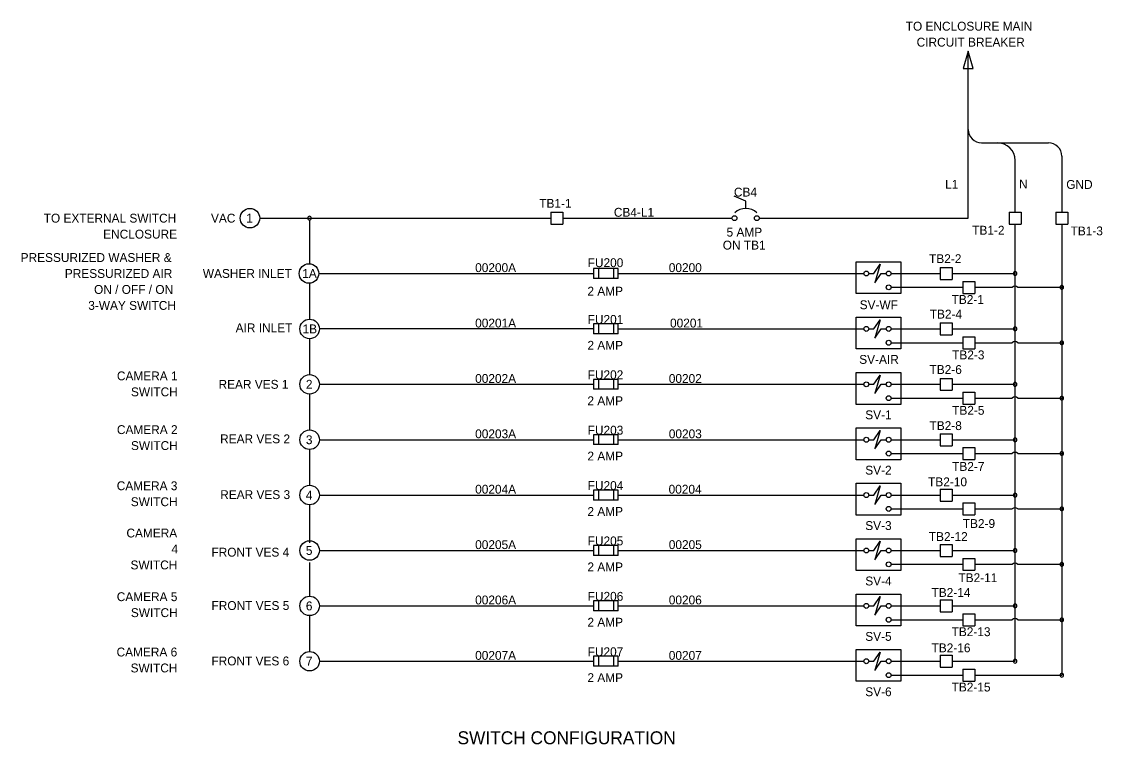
# Model space of a CAD drawing. Extents: x 0.82 to 2.03, y 0.91 to 1.72.
import ezdxf

# ---------------------------------------------------------------- set-up
doc = ezdxf.new("R2010")
doc.units = 0
for name, color, linetype in [('Default', 7, 'Continuous'), ('Sheets_General Details - Sheet Number Text', 7, 'Continuous'), ('Sheets_General Details - Total Sheet Number Text', 7, 'Continuous'), ('Sheets_General Details - Version Text', 7, 'Continuous')]:
    doc.layers.add(name, color=color, linetype=linetype)

# ---------------------------------------------------------------- blocks, each defined once
blk = doc.blocks.new('DOT-F')
at = {"layer": 'Default'}
for start, end in [(0, 180), (180, 0)]:
    blk.add_arc((0, 0), 0.000397, start, end, dxfattribs=at)
blk = doc.blocks.new('ARROW')
at = {"layer": 'Default'}
blk.add_lwpolyline([(0, 0), (-0.00556, 0.00159), (-0.00556, -0.00159)], close=True, dxfattribs=at)

msp = doc.modelspace()

# ---------------------------------------------------------------- linework, layer by layer
at = {"layer": 'Sheets_General Details - Sheet Number Text'}
for p, q in [((1.8822, 1.4994), (1.8822, 1.6878)), ((1.8971, 1.5845), (1.915, 1.5845)), ((1.915, 1.5845), (1.9726, 1.5845)), ((1.9349, 1.5062), (1.9349, 1.5646)), ((1.9875, 1.5695), (1.9875, 1.5062)), ((1.0837, 1.4994), (1.4119, 1.4994)), ((1.4253, 1.4994), (1.6159, 1.4994)), ((1.6467, 1.4994), (1.8822, 1.4994)), ((1.9349, 0.9997), (1.9349, 1.4927)), ((1.9875, 1.4927), (1.9875, 0.984)), ((1.151, 1.437), (1.4596, 1.437)), ((1.4876, 1.437), (1.7645, 1.437)), ((1.7953, 1.437), (1.8505, 1.437)), ((1.8639, 1.437), (1.9349, 1.437)), ((1.7953, 1.4214), (1.876, 1.4214)), ((1.8894, 1.4214), (1.9316, 1.4214)), ((1.9381, 1.4214), (1.9875, 1.4214)), ((1.4598, 1.3745), (1.151, 1.3745)), ((1.4876, 1.3745), (1.7645, 1.3745)), ((1.7953, 1.3745), (1.8505, 1.3745)), ((1.8639, 1.3745), (1.9349, 1.3745)), ((1.7953, 1.3589), (1.876, 1.3589)), ((1.8894, 1.3589), (1.9316, 1.3589)), ((1.9381, 1.3589), (1.9875, 1.3589)), ((1.151, 1.312), (1.4596, 1.312)), ((1.4876, 1.312), (1.7645, 1.312)), ((1.7953, 1.312), (1.8505, 1.312)), ((1.8639, 1.312), (1.9349, 1.312)), ((1.7953, 1.2964), (1.876, 1.2964)), ((1.8894, 1.2964), (1.9316, 1.2964)), ((1.9381, 1.2964), (1.9875, 1.2964)), ((1.1515, 1.2495), (1.4596, 1.2495)), ((1.4876, 1.2495), (1.7645, 1.2495)), ((1.7953, 1.2495), (1.8505, 1.2495)), ((1.8639, 1.2495), (1.9349, 1.2495)), ((1.7953, 1.2339), (1.876, 1.2339)), ((1.8894, 1.2339), (1.9316, 1.2339)), ((1.9381, 1.2339), (1.9875, 1.2339)), ((1.151, 1.1871), (1.4596, 1.1871)), ((1.4876, 1.1871), (1.7645, 1.1871)), ((1.7953, 1.1871), (1.8505, 1.1871)), ((1.8639, 1.1871), (1.9349, 1.1871)), ((1.7953, 1.1715), (1.876, 1.1715)), ((1.8894, 1.1715), (1.9316, 1.1715)), ((1.9381, 1.1715), (1.9875, 1.1715)), ((1.151, 1.1246), (1.4598, 1.1246)), ((1.4876, 1.1246), (1.7645, 1.1246)), ((1.7953, 1.1246), (1.8505, 1.1246)), ((1.8639, 1.1246), (1.9349, 1.1246)), ((1.7953, 1.109), (1.876, 1.109)), ((1.8894, 1.109), (1.9316, 1.109)), ((1.9381, 1.109), (1.9875, 1.109)), ((1.151, 1.0621), (1.4596, 1.0621)), ((1.4876, 1.0621), (1.7645, 1.0621)), ((1.7953, 1.0621), (1.8505, 1.0621)), ((1.8639, 1.0621), (1.9349, 1.0621)), ((1.7953, 1.0465), (1.876, 1.0465)), ((1.8894, 1.0465), (1.9316, 1.0465)), ((1.9381, 1.0465), (1.9875, 1.0465)), ((1.151, 0.9997), (1.4596, 0.9997)), ((1.4876, 0.9997), (1.7645, 0.9997)), ((1.7953, 0.9997), (1.8505, 0.9997)), ((1.8639, 0.9997), (1.9349, 0.9997)), ((1.7953, 0.984), (1.876, 0.984)), ((1.8894, 0.984), (1.9381, 0.984)), ((1.9381, 0.984), (1.9875, 0.984))]:
    msp.add_line(p, q, dxfattribs=at)
for centre, radius, start, end in [((1.8971, 1.5994), 0.0149, 180, 270), ((1.915, 1.5646), 0.0199, 360, 90), ((1.9726, 1.5695), 0.0149, 360, 90), ((1.9349, 1.418), 0.00466, 45.849, 134.151), ((1.9349, 1.3555), 0.00466, 45.849, 134.151), ((1.9349, 1.2931), 0.00466, 45.849, 134.151), ((1.9349, 1.2306), 0.00466, 45.849, 134.151), ((1.9349, 1.1681), 0.00466, 45.849, 134.151), ((1.9349, 1.1056), 0.00466, 45.849, 134.151), ((1.9349, 1.0432), 0.00466, 45.849, 134.151)]:
    msp.add_arc(centre, radius, start, end, dxfattribs=at)
at = {"layer": 'Sheets_General Details - Total Sheet Number Text'}
for p, q in [((1.1399, 1.4975), (1.1399, 1.448)), ((1.1399, 1.4259), (1.1399, 1.3855)), ((1.1399, 1.3635), (1.1399, 1.3231)), ((1.1399, 1.301), (1.1399, 1.2606)), ((1.1399, 1.2385), (1.1399, 1.1981)), ((1.1399, 1.176), (1.1399, 1.1333)), ((1.1399, 1.1112), (1.1399, 1.0732)), ((1.1399, 1.0511), (1.1399, 1.0107))]:
    msp.add_line(p, q, dxfattribs=at)
for centre in [(1.0727, 1.4994), (1.1392, 1.437), (1.1399, 1.3745), (1.1399, 1.312), (1.1399, 1.2495), (1.1399, 1.1871), (1.1399, 1.1246), (1.1399, 1.0621), (1.1399, 0.9997)]:
    msp.add_circle(centre, 0.011, dxfattribs=at)
at = {"layer": 'Sheets_General Details - Version Text'}
for p, q in [((1.6315, 1.5184), (1.6185, 1.5244)), ((1.6315, 1.5104), (1.6315, 1.5184)), ((1.4119, 1.5062), (1.4253, 1.5062)), ((1.4119, 1.5062), (1.4119, 1.4927)), ((1.4253, 1.5062), (1.4253, 1.4927)), ((1.9281, 1.5062), (1.9416, 1.5062)), ((1.9281, 1.5062), (1.9281, 1.4927)), ((1.9416, 1.5062), (1.9416, 1.4927)), ((1.9808, 1.5062), (1.9942, 1.5062)), ((1.9808, 1.5062), (1.9808, 1.4927)), ((1.9942, 1.5062), (1.9942, 1.4927)), ((1.4119, 1.4927), (1.4253, 1.4927)), ((1.9281, 1.4927), (1.9416, 1.4927)), ((1.9808, 1.4927), (1.9942, 1.4927)), ((1.4878, 1.4426), (1.4598, 1.4426)), ((1.4598, 1.4426), (1.4598, 1.4314)), ((1.4654, 1.4426), (1.4654, 1.4314)), ((1.4822, 1.4426), (1.4822, 1.4314)), ((1.4878, 1.4314), (1.4878, 1.4426)), ((1.7756, 1.437), (1.7828, 1.4474)), ((1.7828, 1.4474), (1.777, 1.4265)), ((1.8505, 1.4437), (1.8639, 1.4437)), ((1.8505, 1.4437), (1.8505, 1.4303)), ((1.8639, 1.4437), (1.8639, 1.4303)), ((1.4878, 1.4314), (1.4598, 1.4314)), ((1.7701, 1.437), (1.7756, 1.437)), ((1.777, 1.4265), (1.7842, 1.437)), ((1.7842, 1.437), (1.7897, 1.437)), ((1.8505, 1.4303), (1.8639, 1.4303)), ((1.876, 1.4281), (1.8894, 1.4281)), ((1.876, 1.4281), (1.876, 1.4146)), ((1.8894, 1.4281), (1.8894, 1.4146)), ((1.876, 1.4146), (1.8894, 1.4146)), ((1.4878, 1.3801), (1.4598, 1.3801)), ((1.4598, 1.3801), (1.4598, 1.3689)), ((1.4654, 1.3801), (1.4654, 1.3689)), ((1.4822, 1.3801), (1.4822, 1.3689)), ((1.4878, 1.3689), (1.4878, 1.3801)), ((1.7756, 1.3745), (1.7828, 1.3849)), ((1.7828, 1.3849), (1.777, 1.3641)), ((1.8505, 1.3812), (1.8639, 1.3812)), ((1.8505, 1.3812), (1.8505, 1.3678)), ((1.8639, 1.3812), (1.8639, 1.3678)), ((1.4878, 1.3689), (1.4598, 1.3689)), ((1.7701, 1.3745), (1.7756, 1.3745)), ((1.777, 1.3641), (1.7842, 1.3745)), ((1.7842, 1.3745), (1.7897, 1.3745)), ((1.8505, 1.3678), (1.8639, 1.3678)), ((1.876, 1.3656), (1.8894, 1.3656)), ((1.876, 1.3656), (1.876, 1.3522)), ((1.8894, 1.3656), (1.8894, 1.3522)), ((1.876, 1.3522), (1.8894, 1.3522)), ((1.4598, 1.3176), (1.4598, 1.3064)), ((1.4878, 1.3176), (1.4598, 1.3176)), ((1.4654, 1.3176), (1.4654, 1.3064)), ((1.4822, 1.3176), (1.4822, 1.3064)), ((1.4878, 1.3064), (1.4878, 1.3176)), ((1.7756, 1.312), (1.7828, 1.3225)), ((1.7828, 1.3225), (1.777, 1.3016)), ((1.8505, 1.3187), (1.8639, 1.3187)), ((1.8505, 1.3187), (1.8505, 1.3053)), ((1.8639, 1.3187), (1.8639, 1.3053)), ((1.4878, 1.3064), (1.4598, 1.3064)), ((1.7701, 1.312), (1.7756, 1.312)), ((1.777, 1.3016), (1.7842, 1.312)), ((1.7842, 1.312), (1.7897, 1.312)), ((1.8505, 1.3053), (1.8639, 1.3053)), ((1.876, 1.3031), (1.8894, 1.3031)), ((1.876, 1.3031), (1.876, 1.2897)), ((1.8894, 1.3031), (1.8894, 1.2897)), ((1.876, 1.2897), (1.8894, 1.2897)), ((1.4598, 1.2551), (1.4598, 1.244)), ((1.4878, 1.2551), (1.4598, 1.2551)), ((1.4654, 1.2551), (1.4654, 1.244)), ((1.4822, 1.2551), (1.4822, 1.244)), ((1.4878, 1.244), (1.4878, 1.2551)), ((1.7756, 1.2495), (1.7828, 1.26)), ((1.7828, 1.26), (1.777, 1.2391)), ((1.8505, 1.2563), (1.8639, 1.2563)), ((1.8505, 1.2563), (1.8505, 1.2428)), ((1.8639, 1.2563), (1.8639, 1.2428)), ((1.4878, 1.244), (1.4598, 1.244)), ((1.7701, 1.2495), (1.7756, 1.2495)), ((1.777, 1.2391), (1.7842, 1.2495)), ((1.7842, 1.2495), (1.7897, 1.2495)), ((1.8505, 1.2428), (1.8639, 1.2428)), ((1.876, 1.2407), (1.8894, 1.2407)), ((1.876, 1.2407), (1.876, 1.2272)), ((1.8894, 1.2407), (1.8894, 1.2272)), ((1.876, 1.2272), (1.8894, 1.2272)), ((1.7756, 1.1871), (1.7828, 1.1975)), ((1.7828, 1.1975), (1.777, 1.1766)), ((1.8505, 1.1938), (1.8639, 1.1938)), ((1.8505, 1.1938), (1.8505, 1.1804)), ((1.8639, 1.1938), (1.8639, 1.1804)), ((1.4598, 1.1927), (1.4598, 1.1815)), ((1.4878, 1.1927), (1.4598, 1.1927)), ((1.4878, 1.1815), (1.4598, 1.1815)), ((1.4654, 1.1927), (1.4654, 1.1815)), ((1.4822, 1.1927), (1.4822, 1.1815)), ((1.4878, 1.1815), (1.4878, 1.1927)), ((1.7701, 1.1871), (1.7756, 1.1871)), ((1.777, 1.1766), (1.7842, 1.1871)), ((1.7842, 1.1871), (1.7897, 1.1871)), ((1.8505, 1.1804), (1.8639, 1.1804)), ((1.876, 1.1782), (1.8894, 1.1782)), ((1.876, 1.1782), (1.876, 1.1648)), ((1.8894, 1.1782), (1.8894, 1.1648)), ((1.876, 1.1648), (1.8894, 1.1648)), ((1.7756, 1.1246), (1.7828, 1.135)), ((1.7828, 1.135), (1.777, 1.1142)), ((1.4878, 1.1302), (1.4598, 1.1302)), ((1.4598, 1.1302), (1.4598, 1.119)), ((1.4654, 1.1302), (1.4654, 1.119)), ((1.4822, 1.1302), (1.4822, 1.119)), ((1.4878, 1.119), (1.4878, 1.1302)), ((1.7701, 1.1246), (1.7756, 1.1246)), ((1.777, 1.1142), (1.7842, 1.1246)), ((1.7842, 1.1246), (1.7897, 1.1246)), ((1.8505, 1.1313), (1.8639, 1.1313)), ((1.8505, 1.1313), (1.8505, 1.1179)), ((1.8639, 1.1313), (1.8639, 1.1179)), ((1.4878, 1.119), (1.4598, 1.119)), ((1.8505, 1.1179), (1.8639, 1.1179)), ((1.876, 1.1157), (1.8894, 1.1157)), ((1.876, 1.1157), (1.876, 1.1023)), ((1.8894, 1.1157), (1.8894, 1.1023)), ((1.876, 1.1023), (1.8894, 1.1023)), ((1.7756, 1.0621), (1.7828, 1.0726)), ((1.7828, 1.0726), (1.777, 1.0517)), ((1.4878, 1.0677), (1.4598, 1.0677)), ((1.4598, 1.0677), (1.4598, 1.0565)), ((1.4654, 1.0677), (1.4654, 1.0565)), ((1.4822, 1.0677), (1.4822, 1.0565)), ((1.4878, 1.0565), (1.4878, 1.0677)), ((1.7701, 1.0621), (1.7756, 1.0621)), ((1.777, 1.0517), (1.7842, 1.0621)), ((1.7842, 1.0621), (1.7897, 1.0621)), ((1.8505, 1.0688), (1.8639, 1.0688)), ((1.8505, 1.0688), (1.8505, 1.0554)), ((1.8639, 1.0688), (1.8639, 1.0554)), ((1.4878, 1.0565), (1.4598, 1.0565)), ((1.8505, 1.0554), (1.8639, 1.0554)), ((1.876, 1.0532), (1.8894, 1.0532)), ((1.876, 1.0532), (1.876, 1.0398)), ((1.8894, 1.0532), (1.8894, 1.0398)), ((1.876, 1.0398), (1.8894, 1.0398)), ((1.4878, 1.0053), (1.4598, 1.0053)), ((1.4598, 1.0053), (1.4598, 0.9941)), ((1.4654, 1.0053), (1.4654, 0.9941)), ((1.4822, 1.0053), (1.4822, 0.9941)), ((1.4878, 0.9941), (1.4878, 1.0053)), ((1.7701, 0.9997), (1.7756, 0.9997)), ((1.7756, 0.9997), (1.7828, 1.0101)), ((1.7828, 1.0101), (1.777, 0.9892)), ((1.777, 0.9892), (1.7842, 0.9997)), ((1.7842, 0.9997), (1.7897, 0.9997)), ((1.8505, 1.0064), (1.8639, 1.0064)), ((1.8505, 1.0064), (1.8505, 0.9929)), ((1.8639, 1.0064), (1.8639, 0.9929)), ((1.4878, 0.9941), (1.4598, 0.9941)), ((1.8505, 0.9929), (1.8639, 0.9929)), ((1.876, 0.9908), (1.8894, 0.9908)), ((1.876, 0.9908), (1.876, 0.9773)), ((1.8894, 0.9908), (1.8894, 0.9773)), ((1.876, 0.9773), (1.8894, 0.9773))]:
    msp.add_line(p, q, dxfattribs=at)
for points in [[(1.7559, 1.4503), (1.8061, 1.4503), (1.8061, 1.4144), (1.7559, 1.4144)], [(1.7559, 1.3878), (1.8061, 1.3878), (1.8061, 1.3519), (1.7559, 1.3519)], [(1.7559, 1.3253), (1.8061, 1.3253), (1.8061, 1.2894), (1.7559, 1.2894)], [(1.7559, 1.2629), (1.8061, 1.2629), (1.8061, 1.227), (1.7559, 1.227)], [(1.7559, 1.2004), (1.8061, 1.2004), (1.8061, 1.1645), (1.7559, 1.1645)], [(1.7559, 1.1379), (1.8061, 1.1379), (1.8061, 1.102), (1.7559, 1.102)], [(1.7559, 1.0755), (1.8061, 1.0755), (1.8061, 1.0395), (1.7559, 1.0395)], [(1.7559, 1.013), (1.8061, 1.013), (1.8061, 0.9771), (1.7559, 0.9771)]]:
    msp.add_lwpolyline(points, close=True, dxfattribs=at)
for centre in [(1.6187, 1.4994), (1.6439, 1.4994), (1.7673, 1.437), (1.7925, 1.437), (1.7925, 1.4214), (1.7673, 1.3745), (1.7925, 1.3745), (1.7925, 1.3589), (1.7673, 1.312), (1.7925, 1.312), (1.7925, 1.2964), (1.7673, 1.2495), (1.7925, 1.2495), (1.7925, 1.2339), (1.7673, 1.1871), (1.7925, 1.1871), (1.7925, 1.1715), (1.7673, 1.1246), (1.7925, 1.1246), (1.7925, 1.109), (1.7673, 1.0621), (1.7925, 1.0621), (1.7925, 1.0465), (1.7673, 0.9997), (1.7925, 0.9997), (1.7925, 0.984)]:
    msp.add_circle(centre, 0.00279, dxfattribs=at)
msp.add_arc((1.6315, 1.4923), 0.0181, 46.3583, 133.6417, dxfattribs=at)

# ---------------------------------------------------------------- block references
at = {"layer": 'Sheets_General Details - Sheet Number Text'}
for name, p, xscale, yscale, rotation in [('ARROW', (1.8822, 1.6878), 3.524598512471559, 3.524598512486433, 89.99999999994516), ('DOT-F', (1.1399, 1.4994), 5.28689776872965, 5.286897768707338, -5.484581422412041e-11), ('DOT-F', (1.9349, 1.437), 5.28689776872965, 5.286897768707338, -5.484581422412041e-11), ('DOT-F', (1.9875, 1.4214), 5.28689776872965, 5.286897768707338, -5.484581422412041e-11), ('DOT-F', (1.9349, 1.3745), 5.28689776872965, 5.286897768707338, -5.484581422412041e-11), ('DOT-F', (1.9875, 1.3589), 5.28689776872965, 5.286897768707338, -5.484581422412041e-11), ('DOT-F', (1.9349, 1.312), 5.28689776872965, 5.286897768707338, -5.484581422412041e-11), ('DOT-F', (1.9875, 1.2964), 5.28689776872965, 5.286897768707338, -5.484581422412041e-11), ('DOT-F', (1.9349, 1.2495), 5.28689776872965, 5.286897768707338, -5.484581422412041e-11), ('DOT-F', (1.9875, 1.2339), 5.28689776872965, 5.286897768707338, -5.484581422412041e-11), ('DOT-F', (1.9349, 1.1871), 5.28689776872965, 5.286897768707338, -5.484581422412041e-11), ('DOT-F', (1.9875, 1.1715), 5.28689776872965, 5.286897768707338, -5.484581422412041e-11), ('DOT-F', (1.9349, 1.1246), 5.28689776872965, 5.286897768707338, -5.484581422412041e-11), ('DOT-F', (1.9875, 1.109), 5.28689776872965, 5.286897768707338, -5.484581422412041e-11), ('DOT-F', (1.9349, 1.0621), 5.28689776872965, 5.286897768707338, -5.484581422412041e-11), ('DOT-F', (1.9875, 1.0465), 5.28689776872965, 5.286897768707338, -5.484581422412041e-11), ('DOT-F', (1.9349, 0.9997), 5.28689776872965, 5.286897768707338, -5.484581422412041e-11), ('DOT-F', (1.9875, 0.984), 5.28689776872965, 5.286897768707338, -5.484581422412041e-11)]:
    msp.add_blockref(name, p, dxfattribs=dict(at, xscale=xscale, yscale=yscale, rotation=rotation))

# ---------------------------------------------------------------- texts
at = {"layer": 'Sheets_General Details - Total Sheet Number Text'}
for s, p in [('TO ENCLOSURE MAIN ', (1.8117, 1.7109)), ('CIRCUIT BREAKER', (1.824, 1.6929)), ('L1', (1.8561, 1.5326)), ('N', (1.9394, 1.5329)), ('GND', (1.9926, 1.5324)), ('CB4', (1.6181, 1.5238)), ('TB1-1', (1.3987, 1.5111)), ('CB4-L1', (1.4828, 1.501)), ('TO EXTERNAL SWITCH', (0.8403, 1.4944)), ('VAC', (1.0288, 1.4944)), ('1', (1.0685, 1.4944)), (' ENCLOSURE', (0.9036, 1.4764)), ('5 AMP', (1.6098, 1.4786)), ('TB1-2', (1.8866, 1.4808)), ('TB1-3', (1.9975, 1.48)), ('ON TB1', (1.6055, 1.464)), ('PRESSURIZED WASHER & ', (0.8143, 1.45)), ('FU200', (1.4533, 1.4442)), ('TB2-2', (1.838, 1.4487)), ('PRESSURIZED AIR ', (0.8641, 1.432)), ('WASHER INLET', (1.0196, 1.432)), ('1A', (1.1316, 1.432)), ('00200A', (1.3265, 1.4386)), ('00200', (1.5447, 1.4386)), ('ON / OFF / ON ', (0.897, 1.414)), ('2 AMP', (1.453, 1.4121)), ('TB2-1', (1.8634, 1.4027)), ('3-WAY SWITCH', (0.8905, 1.396)), ('SV-WF', (1.7598, 1.3967)), ('FU201', (1.4533, 1.3802)), ('TB2-4', (1.8388, 1.3862)), ('AIR INLET', (1.0566, 1.3707)), ('1B', (1.132, 1.3695)), ('00201A', (1.3265, 1.3761)), ('00201', (1.5461, 1.3761)), ('2 AMP', (1.453, 1.351)), ('SV-AIR', (1.7593, 1.3351)), ('TB2-3', (1.864, 1.3402)), ('FU202', (1.4533, 1.3178)), ('TB2-6', (1.8385, 1.3237)), ('CAMERA 1', (0.9228, 1.3165)), ('REAR VES 1', (1.0373, 1.307)), ('2', (1.1357, 1.307)), ('00202A', (1.3265, 1.3136)), ('00202', (1.5447, 1.3136)), (' SWITCH', (0.9349, 1.2985)), ('2 AMP', (1.453, 1.2885)), ('SV-1', (1.7661, 1.2726)), ('TB2-5', (1.864, 1.2777)), ('TB2-8', (1.8385, 1.2604)), ('CAMERA 2', (0.9228, 1.2559)), ('REAR VES 2', (1.0391, 1.2455)), ('3', (1.1357, 1.2445)), ('00203A', (1.3265, 1.2512)), ('FU203', (1.4533, 1.2553)), ('00203', (1.5447, 1.2512)), (' SWITCH', (0.9349, 1.2379)), ('2 AMP', (1.453, 1.2261)), ('SV-2', (1.7661, 1.2102)), ('TB2-7', (1.864, 1.2144)), ('TB2-10', (1.8369, 1.197)), ('CAMERA 3', (0.9226, 1.1926)), ('00204A', (1.3265, 1.1887)), ('FU204', (1.4533, 1.1928)), ('00204', (1.5445, 1.1887)), (' SWITCH', (0.9347, 1.1746)), ('REAR VES 3', (1.0392, 1.1826)), ('4', (1.1357, 1.1821)), ('2 AMP', (1.453, 1.1636)), ('SV-3', (1.7661, 1.1477)), ('TB2-9', (1.876, 1.15)), ('CAMERA', (0.9335, 1.1393)), ('TB2-12', (1.8377, 1.1353)), ('00205A', (1.3265, 1.1262)), ('FU205', (1.4533, 1.1304)), ('00205', (1.5447, 1.1262)), (' 4', (0.9805, 1.1213)), ('FRONT VES 4', (1.0293, 1.1177)), ('5', (1.1357, 1.1196)), (' SWITCH', (0.9344, 1.1033)), ('2 AMP', (1.453, 1.1011)), ('TB2-11', (1.8711, 1.0889)), ('SV-4', (1.7661, 1.0852)), ('CAMERA 5', (0.9226, 1.0675)), ('00206A', (1.3265, 1.0638)), ('FU206', (1.4533, 1.0679)), ('00206', (1.5447, 1.0638)), ('TB2-14', (1.8408, 1.0723)), (' SWITCH', (0.9348, 1.0495)), ('FRONT VES 5', (1.0294, 1.0575)), ('6', (1.1357, 1.0571)), ('2 AMP', (1.453, 1.0387)), ('TB2-13', (1.8634, 1.028)), ('SV-5', (1.7661, 1.0227)), ('CAMERA 6', (0.9224, 1.0051)), ('00207A', (1.3265, 1.0013)), ('FU207', (1.4533, 1.0054)), ('00207', (1.5447, 1.0013)), ('TB2-16', (1.8408, 1.0098)), ('FRONT VES 6', (1.0293, 0.995)), ('7', (1.1357, 0.9947)), (' SWITCH', (0.9345, 0.9871)), ('2 AMP', (1.453, 0.9762)), ('TB2-15', (1.8634, 0.9656)), ('SV-6', (1.7661, 0.9603))]:
    msp.add_text(s, height=0.01, rotation=360, dxfattribs=at).set_placement(p)
msp.add_text('SWITCH CONFIGURATION', height=0.014583, dxfattribs=at).set_placement((1.3066, 0.9061))

doc.saveas('drawing.dxf')
